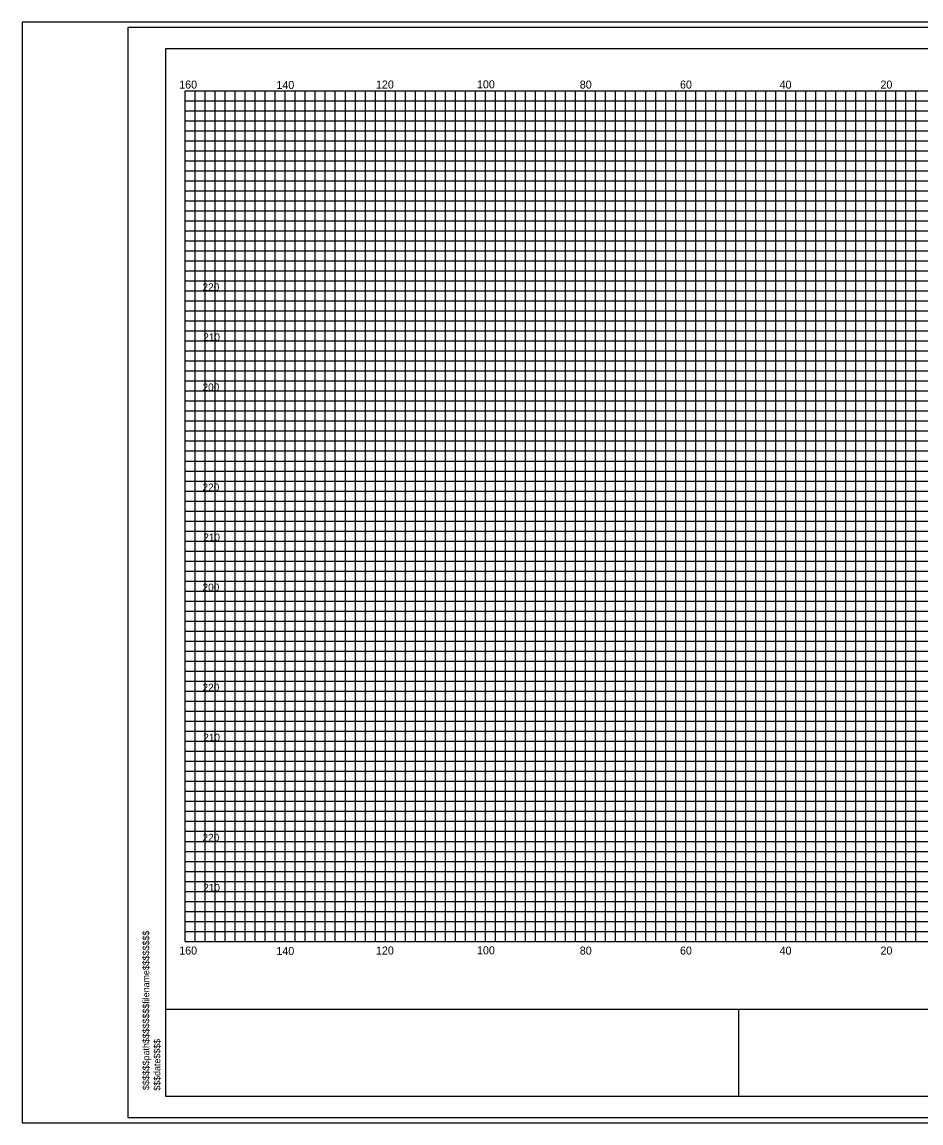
# Model space of a CAD drawing. Extents: x 967 to 1326, y 964 to 2584.
# Drawn here: x 967.4 to 1147, y 1523.7 to 1743.7 of the extents above; entities that cross this region are included whole.
import ezdxf

# ---------------------------------------------------------------- set-up
doc = ezdxf.new("R2010")
doc.units = 0
for name, color, linetype in [('Default', 7, 'Continuous'), ('RD_GPK_XS_Cell', 7, 'Continuous'), ('RD_XS_ExGround', 7, 'Continuous'), ('RD_XS_ExPaveRet', 7, 'Continuous'), ('RD_XS_Misc_Line', 7, 'Continuous'), ('RD_XS_TX_Elev_EX', 7, 'Continuous')]:
    doc.layers.add(name, color=color, linetype=linetype)

msp = doc.modelspace()

# ---------------------------------------------------------------- linework, layer by layer
at = {"layer": 'RD_GPK_XS_Cell'}
for p, q in [((1000, 1730), (1320, 1730)), ((1000, 1560), (1000, 1730)), ((1010, 1560), (1010, 1730)), ((1020, 1560), (1020, 1730)), ((1030, 1560), (1030, 1730)), ((1040, 1560), (1040, 1730)), ((1050, 1560), (1050, 1730)), ((1060, 1560), (1060, 1730)), ((1070, 1560), (1070, 1730)), ((1080, 1560), (1080, 1730)), ((1090, 1560), (1090, 1730)), ((1100, 1560), (1100, 1730)), ((1110, 1560), (1110, 1730)), ((1120, 1560), (1120, 1730)), ((1130, 1560), (1130, 1730)), ((1140, 1560), (1140, 1730)), ((1000, 1720), (1320, 1720)), ((1000, 1710), (1320, 1710)), ((1000, 1700), (1320, 1700)), ((1000, 1690), (1320, 1690)), ((1000, 1680), (1320, 1680)), ((1000, 1670), (1320, 1670)), ((1000, 1660), (1320, 1660)), ((1000, 1650), (1320, 1650)), ((1000, 1640), (1320, 1640)), ((1000, 1630), (1320, 1630)), ((1000, 1620), (1320, 1620)), ((1000, 1610), (1320, 1610)), ((1000, 1600), (1320, 1600)), ((1000, 1590), (1320, 1590)), ((1000, 1580), (1320, 1580)), ((1000, 1570), (1320, 1570)), ((1000, 1560), (1320, 1560))]:
    msp.add_line(p, q, dxfattribs=at)
at = {"layer": 'RD_XS_ExGround'}
for p, q in [((1002, 1560), (1002, 1730)), ((1004, 1560), (1004, 1730)), ((1006, 1560), (1006, 1730)), ((1008, 1560), (1008, 1730)), ((1012, 1560), (1012, 1730)), ((1014, 1560), (1014, 1730)), ((1016, 1560), (1016, 1730)), ((1018, 1560), (1018, 1730)), ((1022, 1560), (1022, 1730)), ((1024, 1560), (1024, 1730)), ((1026, 1560), (1026, 1730)), ((1028, 1560), (1028, 1730)), ((1032, 1560), (1032, 1730)), ((1034, 1560), (1034, 1730)), ((1036, 1560), (1036, 1730)), ((1038, 1560), (1038, 1730)), ((1042, 1560), (1042, 1730)), ((1044, 1560), (1044, 1730)), ((1046, 1560), (1046, 1730)), ((1048, 1560), (1048, 1730)), ((1052, 1560), (1052, 1730)), ((1054, 1560), (1054, 1730)), ((1056, 1560), (1056, 1730)), ((1058, 1560), (1058, 1730)), ((1062, 1560), (1062, 1730)), ((1064, 1560), (1064, 1730)), ((1066, 1560), (1066, 1730)), ((1068, 1560), (1068, 1730)), ((1072, 1560), (1072, 1730)), ((1074, 1560), (1074, 1730)), ((1076, 1560), (1076, 1730)), ((1078, 1560), (1078, 1730)), ((1082, 1560), (1082, 1730)), ((1084, 1560), (1084, 1730)), ((1086, 1560), (1086, 1730)), ((1088, 1560), (1088, 1730)), ((1092, 1560), (1092, 1730)), ((1094, 1560), (1094, 1730)), ((1096, 1560), (1096, 1730)), ((1098, 1560), (1098, 1730)), ((1102, 1560), (1102, 1730)), ((1104, 1560), (1104, 1730)), ((1106, 1560), (1106, 1730)), ((1108, 1560), (1108, 1730)), ((1112, 1560), (1112, 1730)), ((1114, 1560), (1114, 1730)), ((1116, 1560), (1116, 1730)), ((1118, 1560), (1118, 1730)), ((1122, 1560), (1122, 1730)), ((1124, 1560), (1124, 1730)), ((1126, 1560), (1126, 1730)), ((1128, 1560), (1128, 1730)), ((1132, 1560), (1132, 1730)), ((1134, 1560), (1134, 1730)), ((1136, 1560), (1136, 1730)), ((1138, 1560), (1138, 1730)), ((1142, 1560), (1142, 1730)), ((1144, 1560), (1144, 1730)), ((1146, 1560), (1146, 1730)), ((1000, 1728), (1320, 1728)), ((1000, 1726), (1320, 1726)), ((1000, 1724), (1320, 1724)), ((1000, 1722), (1320, 1722)), ((1000, 1718), (1320, 1718)), ((1000, 1716), (1320, 1716)), ((1000, 1714), (1320, 1714)), ((1000, 1712), (1320, 1712)), ((1000, 1708), (1320, 1708)), ((1000, 1706), (1320, 1706)), ((1000, 1704), (1320, 1704)), ((1000, 1702), (1320, 1702)), ((1000, 1698), (1320, 1698)), ((1000, 1696), (1320, 1696)), ((1000, 1694), (1320, 1694)), ((1000, 1692), (1320, 1692)), ((1000, 1688), (1320, 1688)), ((1000, 1686), (1320, 1686)), ((1000, 1684), (1320, 1684)), ((1000, 1682), (1320, 1682)), ((1000, 1678), (1320, 1678)), ((1000, 1676), (1320, 1676)), ((1000, 1674), (1320, 1674)), ((1000, 1672), (1320, 1672)), ((1000, 1668), (1320, 1668)), ((1000, 1666), (1320, 1666)), ((1000, 1664), (1320, 1664)), ((1000, 1662), (1320, 1662)), ((1000, 1658), (1320, 1658)), ((1000, 1656), (1320, 1656)), ((1000, 1654), (1320, 1654)), ((1000, 1652), (1320, 1652)), ((1000, 1648), (1320, 1648)), ((1000, 1646), (1320, 1646)), ((1000, 1644), (1320, 1644)), ((1000, 1642), (1320, 1642)), ((1000, 1638), (1320, 1638)), ((1000, 1636), (1320, 1636)), ((1000, 1634), (1320, 1634)), ((1000, 1632), (1320, 1632)), ((1000, 1628), (1320, 1628)), ((1000, 1626), (1320, 1626)), ((1000, 1624), (1320, 1624)), ((1000, 1622), (1320, 1622)), ((1000, 1618), (1320, 1618)), ((1000, 1616), (1320, 1616)), ((1000, 1614), (1320, 1614)), ((1000, 1612), (1320, 1612)), ((1000, 1608), (1320, 1608)), ((1000, 1606), (1320, 1606)), ((1000, 1604), (1320, 1604)), ((1000, 1602), (1320, 1602)), ((1000, 1598), (1320, 1598)), ((1000, 1596), (1320, 1596)), ((1000, 1594), (1320, 1594)), ((1000, 1592), (1320, 1592)), ((1000, 1588), (1320, 1588)), ((1000, 1586), (1320, 1586)), ((1000, 1584), (1320, 1584)), ((1000, 1582), (1320, 1582)), ((1000, 1578), (1320, 1578)), ((1000, 1576), (1320, 1576)), ((1000, 1574), (1320, 1574)), ((1000, 1572), (1320, 1572)), ((1000, 1568), (1320, 1568)), ((1000, 1566), (1320, 1566)), ((1000, 1564), (1320, 1564)), ((1000, 1562), (1320, 1562))]:
    msp.add_line(p, q, dxfattribs=at)
at = {"layer": 'RD_XS_ExPaveRet'}
for points in [[(967.41, 1523.72), (1326.28, 1523.72), (1326.28, 1743.72), (967.41, 1743.72)], [(988.52, 1524.84), (1326.28, 1524.84), (1326.28, 1742.6), (988.52, 1742.6)]]:
    msp.add_lwpolyline(points, close=True, dxfattribs=at)
at = {"layer": 'RD_XS_TX_Elev_EX'}
for p, q in [((996.11, 1528.98), (996.11, 1738.46)), ((996.11, 1738.46), (1323.89, 1738.46)), ((996.11, 1546.49), (1323.89, 1546.49)), ((1110.59, 1528.98), (1110.59, 1546.56)), ((1323.89, 1528.98), (996.11, 1528.98))]:
    msp.add_line(p, q, dxfattribs=at)

# ---------------------------------------------------------------- texts
at = {"layer": 'Default'}
for s, p in [('220', (1003.47, 1690)), ('210', (1003.61, 1680)), ('200', (1003.47, 1670)), ('220', (1003.47, 1650)), ('210', (1003.61, 1640)), ('200', (1003.47, 1630)), ('220', (1003.47, 1610)), ('210', (1003.61, 1600)), ('220', (1003.47, 1580)), ('210', (1003.61, 1570))]:
    msp.add_text(s, height=1.5, dxfattribs=at).set_placement(p)
for s, p in [('$$$$$$path$$$$$$$$filename$$$$$$$$', (992.83, 1530.31)), ('$$$date$$$$', (995.04, 1530.17))]:
    msp.add_text(s, height=1.3258, rotation=90, dxfattribs=at).set_placement(p)
at = {"layer": 'RD_XS_Misc_Line'}
for s, p in [('160', (998.81, 1730.42)), ('140', (1018.23, 1730.34)), ('120', (1038.12, 1730.43)), ('100', (1058.3, 1730.47)), ('80', (1078.84, 1730.42)), ('60', (1098.86, 1730.42)), ('40', (1118.75, 1730.41)), ('20', (1138.91, 1730.42)), ('160', (998.81, 1557.37)), ('140', (1018.23, 1557.29)), ('120', (1038.12, 1557.38)), ('100', (1058.3, 1557.42)), ('80', (1078.84, 1557.37)), ('60', (1098.86, 1557.37)), ('40', (1118.75, 1557.36)), ('20', (1138.91, 1557.37))]:
    msp.add_text(s, height=1.6, dxfattribs=at).set_placement(p)

doc.saveas('drawing.dxf')
